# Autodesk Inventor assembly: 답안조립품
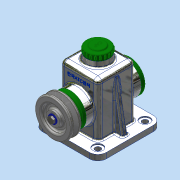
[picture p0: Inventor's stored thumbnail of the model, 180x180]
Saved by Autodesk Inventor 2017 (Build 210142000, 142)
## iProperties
Part Number: 답안조립품
Material: 일반
Document SubType Name: Assembly
Designer: MRC
Author: MRC
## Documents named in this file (14)
- C:\Users\MRC\Desktop\700907V1009\답안조립품.iam
- C:\Users\MRC\Desktop\700907V1009\본체.ipt
- C:\Users\MRC\Desktop\700907V1009\Ű 5 x 5 x 14.ipt
- C:\Users\MRC\Desktop\700907V1009\V-벨트풀리.ipt
- C:\Users\MRC\Desktop\700907V1009\뒤커버.ipt
- C:\Users\MRC\Desktop\700907V1009\멈춤링 15 x 1.ipt
- C:\Users\MRC\Desktop\700907V1009\베어링 15 x 35 x 11.ipt
- C:\Users\MRC\Desktop\700907V1009\볼트 M4 x 10.ipt
- C:\Users\MRC\Desktop\700907V1009\볼트 M6 x 12.ipt
- C:\Users\MRC\Desktop\700907V1009\상부캡.ipt
- C:\Users\MRC\Desktop\700907V1009\앞커버.ipt
- C:\Users\MRC\Desktop\700907V1009\오일실 15 25 7.ipt
- C:\Users\MRC\Desktop\700907V1009\와셔.ipt
- C:\Users\MRC\Desktop\700907V1009\축.ipt
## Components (2 placed, 2 different names)
1. Ű 5 x 5 x 14:1
2. V-벨트풀리:1
